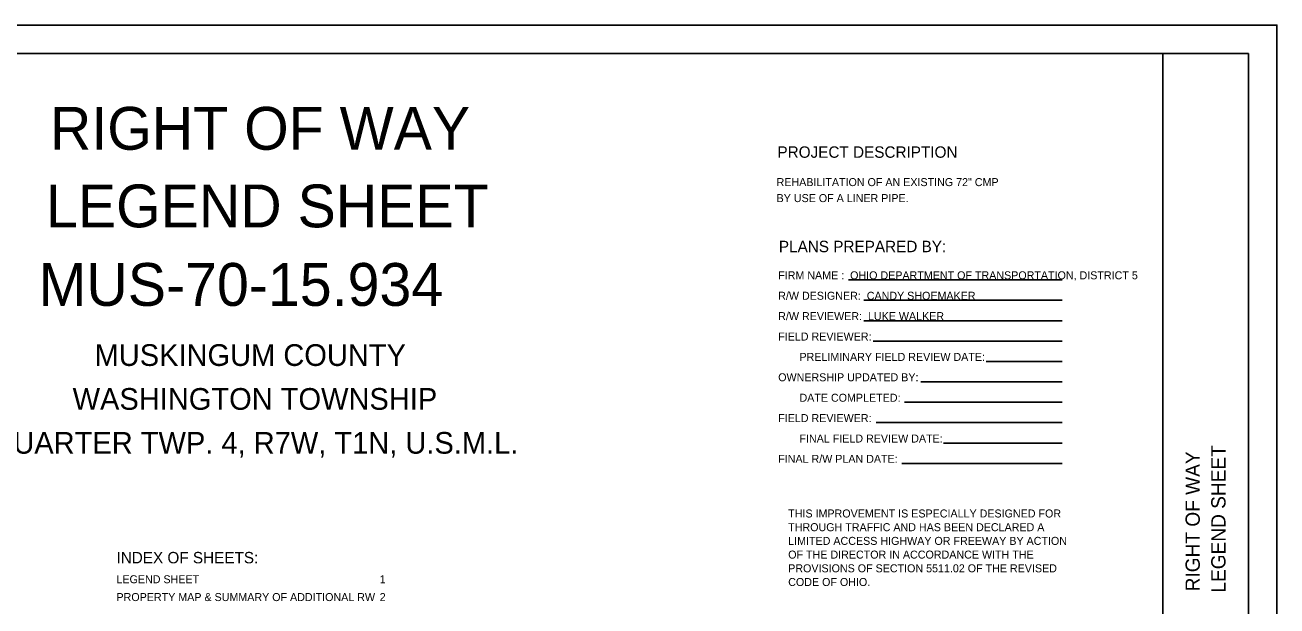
# Model space of a CAD drawing. Extents: x 0 to 34, y 0 to 22.
# Drawn here: x 12.09 to 34, y 11.83 to 22 of the extents above; entities that cross this region are included whole.
import ezdxf

# ---------------------------------------------------------------- set-up
doc = ezdxf.new("R2010")
doc.units = 0
for name, color, linetype in [('Default', 7, 'Continuous'), ('SH_Border', 7, 'Continuous'), ('SH_Cut_Line', 7, 'Continuous'), ('SH_Data', 7, 'Continuous'), ('SH_Text', 7, 'Continuous')]:
    doc.layers.add(name, color=color, linetype=linetype)

msp = doc.modelspace()

# ---------------------------------------------------------------- linework, layer by layer
at = {"layer": 'SH_Border'}
msp.add_line((32, 0.5), (32, 21.5), dxfattribs=at)
msp.add_lwpolyline([(1.5, 21.5), (33.5, 21.5), (33.5, 0.5), (1.5, 0.5)], close=True, dxfattribs=at)
at = {"layer": 'SH_Cut_Line'}
msp.add_lwpolyline([(0, 0), (34, 0), (34, 22), (0, 22)], close=True, dxfattribs=at)
at = {"layer": 'SH_Text'}
for p, q in [((26.504, 17.537), (30.241, 17.537)), ((26.768, 17.18), (30.241, 17.18)), ((26.768, 16.822), (30.241, 16.822)), ((26.932, 16.465), (30.241, 16.465)), ((28.914, 16.108), (30.241, 16.108)), ((27.768, 15.751), (30.241, 15.751)), ((27.483, 15.394), (30.241, 15.394)), ((26.986, 15.037), (30.241, 15.037)), ((28.166, 14.679), (30.241, 14.679)), ((27.438, 14.323), (30.241, 14.323))]:
    msp.add_line(p, q, dxfattribs=at)

# ---------------------------------------------------------------- texts
at = {"layer": 'Default'}
for s, height, p in [('PROJECT DESCRIPTION', 0.2, (25.259, 19.675)), ('REHABILITATION OF AN EXISTING 72" CMP', 0.14, (25.244, 19.179)), ('BY USE OF A LINER PIPE.', 0.14, (25.244, 18.899))]:
    msp.add_text(s, height=height, dxfattribs=at).set_placement(p)
at = {"layer": 'SH_Data'}
for s, height, p in [('RIGHT OF WAY', 0.75, (12.527, 19.816)), ('LEGEND SHEET', 0.75, (12.458, 18.457)), ('MUS-70-15.934', 0.75, (12.33, 17.082)), ('MUSKINGUM COUNTY', 0.38, (13.309, 16.03)), ('WASHINGTON TOWNSHIP', 0.38, (12.925, 15.262)), ('QUARTER TWP. 4, R7W, T1N, U.S.M.L.', 0.38, (11.492, 14.493)), ('INDEX OF SHEETS:', 0.2, (13.692, 12.573)), ('LEGEND SHEET', 0.14, (13.692, 12.224)), ('     1', 0.14, (18.038, 12.224)), ('PROPERTY MAP & SUMMARY OF ADDITIONAL RW', 0.14, (13.692, 11.912)), ('     2', 0.14, (18.038, 11.912))]:
    msp.add_text(s, height=height, dxfattribs=at).set_placement(p)
for s, p in [('RIGHT OF WAY', (32.65, 12.082)), ('LEGEND SHEET', (33.1, 12.06))]:
    msp.add_text(s, height=0.25, rotation=90, dxfattribs=at).set_placement(p)
at = {"layer": 'SH_Text'}
for s, height, p in [('PLANS PREPARED BY:', 0.2, (25.284, 18.022)), ('FIRM NAME :  OHIO DEPARTMENT OF TRANSPORTATION, DISTRICT 5', 0.14, (25.272, 17.547)), ('R/W DESIGNER:  CANDY SHOEMAKER', 0.14, (25.272, 17.189)), ('R/W REVIEWER:  LUKE WALKER', 0.14, (25.272, 16.832)), ('FIELD REVIEWER:', 0.14, (25.272, 16.475)), ('PRELIMINARY FIELD REVIEW DATE:', 0.14, (25.644, 16.118)), ('OWNERSHIP UPDATED BY:', 0.14, (25.272, 15.761)), ('DATE COMPLETED:', 0.14, (25.644, 15.403)), ('FIELD REVIEWER:', 0.14, (25.272, 15.047)), ('FINAL FIELD REVIEW DATE:', 0.14, (25.644, 14.689)), ('FINAL R/W PLAN DATE:', 0.14, (25.272, 14.333)), ('THIS IMPROVEMENT IS ESPECIALLY DESIGNED FOR', 0.14, (25.447, 13.376)), ('THROUGH TRAFFIC AND HAS BEEN DECLARED A', 0.14, (25.447, 13.136)), ('LIMITED ACCESS HIGHWAY OR FREEWAY BY ACTION', 0.14, (25.447, 12.896)), ('OF THE DIRECTOR IN ACCORDANCE WITH THE', 0.14, (25.447, 12.656)), ('PROVISIONS OF SECTION 5511.02 OF THE REVISED', 0.14, (25.447, 12.416)), ('CODE OF OHIO.', 0.14, (25.447, 12.176))]:
    msp.add_text(s, height=height, dxfattribs=at).set_placement(p)

doc.saveas('drawing.dxf')
